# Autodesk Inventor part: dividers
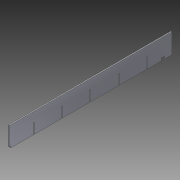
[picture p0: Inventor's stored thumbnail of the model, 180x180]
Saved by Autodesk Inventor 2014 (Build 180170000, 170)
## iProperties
Created: 2014-05
Part Number: dividers
Material: ABS Plastic
Document SubType Name: Modeling
Designer: t_emanb
Density: 1 g/cm^3
Appearance: Smooth - White
Author: t_emanb
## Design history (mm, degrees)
sketch "Sketch1"
  geometry: L1 (0, 0)-(72.39, 0); L2 (72.39, 0)-(72.39, -584.2); L3 (72.39, -584.2)-(0, -584.2); L4 (0, -584.2)-(0, 0); 1 further point
  constraints: 8 end point, 2 parallel, 1 coincident, 1 horizontal, 1 perpendicular
  dimensions: "d0" = 584.2 distance of L1.end L2.end; "d1" = 72.39 distance of L1.start L1.end
extrude "Extrusion1" new body sketch "Sketch1" distance "d2" = 3.048; taper "d3" = 0 deg
sketch "Sketch2" dims "d9" = 25.4, "d18" = 25.4
  geometry: L1 (0, 0)-(584.2, 0) reference; L2 (584.2, 72.39)-(0, 72.39) reference; L3 (88.9, 72.39)-(88.9, 0); L4 (190.5, 72.39)-(190.5, 0); L5 (292.1, 72.39)-(292.1, 0); L6 (393.7, 72.39)-(393.7, 0); L7 (495.3, 72.39)-(495.3, 0); L8 (87.376, 0)-(90.424, 0); L9 (90.424, 0)-(90.424, 38.1); L10 (90.424, 38.1)-(87.376, 38.1); L11 (87.376, 38.1)-(87.376, 0); L12 (188.976, 38.1)-(188.976, 0); L13 (192.024, 38.1)-(188.976, 38.1); L14 (192.024, 0)-(192.024, 38.1); L15 (188.976, 0)-(192.024, 0); L16 (290.576, 38.1)-(290.576, 0); L17 (293.624, 38.1)-(290.576, 38.1); L18 (293.624, 0)-(293.624, 38.1); L19 (290.576, 0)-(293.624, 0); L20 (392.176, 38.1)-(392.176, 0); L21 (395.224, 38.1)-(392.176, 38.1); L22 (395.224, 0)-(395.224, 38.1); L23 (392.176, 0)-(395.224, 0); L24 (493.776, 38.1)-(493.776, 0); L25 (496.824, 38.1)-(493.776, 38.1); L26 (496.824, 0)-(496.824, 38.1); L27 (493.776, 0)-(496.824, 0)
  constraints: 50 end point, 3 horizontal, 3 point on line, 2 parallel, 2 perpendicular, 1 midpoint, 45 other
  dimensions: "d6" = 101.6 distance of L3.start L4.start; "d11" = 3.048 distance of L9.end L10.end; "d12" = 38.1 distance of L10.end L8.start; "d15" = 101.6 distance of L10.end L12.start
extrude "Extrusion2" cut sketch "Sketch2" stored distance "d20" = 3.175; taper "d21" = 0 deg
sketch "Sketch3"
  geometry: L1 (496.824, 0)-(584.2, 0) reference; L2 (584.2, 0)-(584.2, 72.39) reference; L3 (0, 72.39)-(0, 0) reference; L4 (0, 0)-(87.376, 0) reference; L5 (392.176, 0)-(392.176, 38.1) reference; L6 (0, 6.35)-(6.35, 6.35); L7 (6.35, 6.35)-(6.35, 0)
  constraints: 4 end point, 2 perpendicular, 2 point on line
  dimensions: "d26" = 6.35 distance of L6.end L7.end; "d27" = 6.35 distance of L6.start L6.end
extrude "Extrusion3" cut sketch "Sketch3" stored distance "d24" = 25.4; taper "d25" = 0 deg
sketch "Sketch4"
  geometry: L1 (496.824, 0)-(584.2, 0) reference; L2 (584.2, 0)-(584.2, 72.39) reference; L3 (558.8, 9.525)-(546.1, 9.525); L4 (546.1, 9.525)-(546.1, 0); L5 (558.8, 9.525)-(558.8, 0); 1 further point
  constraints: 6 end point, 2 perpendicular, 2 point on line
  dimensions: "d28" = 12.7 distance of L3.start L3.end; "d29" = 9.525 distance between parallel lines of L1 L3; "d30" = 25.4 distance between parallel lines of L2 L5
extrude "Extrusion4" cut sketch "Sketch4" stored distance "d31" = 25.4; taper "d32" = 0 deg
body "Solid1"
